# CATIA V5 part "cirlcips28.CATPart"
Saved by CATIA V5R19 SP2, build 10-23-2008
Part number: cirlcips28
Definition: NONE
Nomenclature: 1
Source: Unknown
Description: PART-1-DESC
Bounding box of the stored display mesh (mm): x -16.639 to 16.639, y -18.581 to 17.45, z -1.2 to 1.2
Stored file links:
  D:\SCHOOL\FRANCE\BANC_POUTRE_EN_MOUSSE\cirlcips28.CATPart
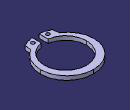
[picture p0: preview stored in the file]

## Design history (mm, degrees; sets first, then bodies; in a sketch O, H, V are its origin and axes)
Body1 "1" (main body)
  Solid1: solid without history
